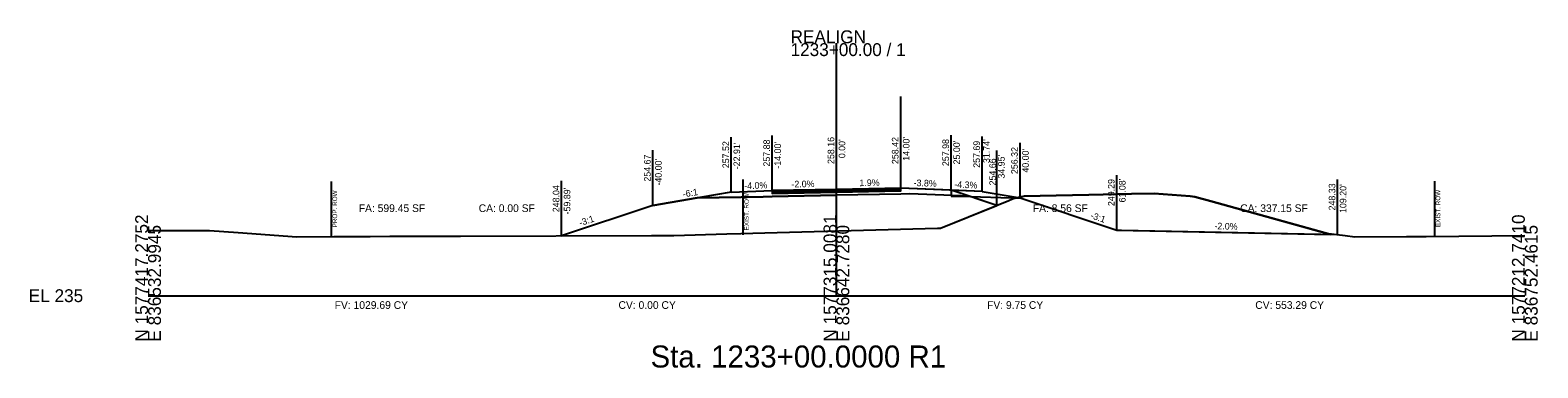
# Model space of a CAD drawing. Extents: x -26 to 6303, y -16 to 9563.
# Drawn here: x 974.3 to 1302.8, y 1984.3 to 2057.8 of the extents above; entities that cross this region are included whole.
import ezdxf

# ---------------------------------------------------------------- set-up
doc = ezdxf.new("R2010")
doc.units = 0
for name, color, linetype in [('ASPHALT_19MM1', 7, 'Continuous'), ('ASPHALT_9_5MM1', 7, 'Continuous'), ('CONST_DCH', 7, 'Continuous'), ('CONST_LV3', 7, 'Continuous'), ('Draft_XS_Grid', 7, 'Continuous'), ('Draft_XS_Text', 7, 'Continuous'), ('DTM_TEMP_DROP', 7, 'Continuous'), ('DTM_X_GROUND', 7, 'Continuous'), ('X_PROFILES_1', 7, 'Continuous'), ('X_TRANS_EOP', 7, 'Continuous'), ('XS_CELL', 7, 'Continuous'), ('XS_M_SHAPES_EARTHWORK', 7, 'Continuous'), ('XS_P_ASPHALT', 7, 'Continuous'), ('XS_P_DR_ASPHALT', 7, 'Continuous'), ('XS_P_GROUND', 7, 'Continuous'), ('XS_P_ROW', 7, 'Continuous'), ('XS_P_SHOULDER', 7, 'Continuous'), ('XS_P_SUBGRADE_GRANULAR', 7, 'Continuous'), ('XS_P_TX_CLEARZONE', 7, 'Continuous'), ('XS_P_TX_FS_BS', 7, 'Continuous'), ('XS_PLAN_CLEAR_ZONE', 7, 'Continuous'), ('XS_SHEET_EW_TX_AREA', 7, 'Continuous'), ('XS_SHEET_EW_TX_VOLUME', 7, 'Continuous'), ('XS_X_ROW', 7, 'Continuous')]:
    doc.layers.add(name, color=color, linetype=linetype)

msp = doc.modelspace()

# ---------------------------------------------------------------- linework, layer by layer
at = {"layer": 'ASPHALT_19MM1'}
msp.add_lwpolyline([(1136, 2022.55), (1136, 2022.28), (1150, 2022.56), (1150, 2022.56), (1164, 2022.82), (1164, 2022.82), (1164, 2023.09), (1164, 2023.09), (1164, 2023.09), (1150, 2022.83), (1150, 2022.83), (1136, 2022.55), (1136, 2022.55)], dxfattribs=at)
at = {"layer": 'ASPHALT_9_5MM1'}
msp.add_lwpolyline([(1136, 2022.88), (1136, 2022.75), (1150, 2023.03), (1150, 2023.03), (1164, 2023.3), (1164, 2023.3), (1164, 2023.42), (1164, 2023.42), (1164, 2023.42), (1150, 2023.16), (1150, 2023.16), (1136, 2022.88), (1136, 2022.88)], dxfattribs=at)
at = {"layer": 'CONST_LV3'}
for points in [[(1110, 2019.67), (1110, 2019.67), (1119.64, 2021.28)], [(1164, 2023.4), (1164, 2023.4), (1150, 2023.16)], [(1181.74, 2022.69), (1181.74, 2022.69), (1164, 2023.4)]]:
    msp.add_lwpolyline(points, dxfattribs=at)
at = {"layer": 'DTM_X_GROUND'}
msp.add_lwpolyline([(1000, 2014.19), (1013.42, 2014.18), (1019.67, 2013.74), (1032.39, 2012.85), (1040.48, 2012.89), (1048.37, 2012.92), (1052.65, 2012.94), (1068.1, 2012.99), (1109.67, 2013.1), (1114.58, 2013.12), (1126.12, 2013.44), (1129.18, 2013.52), (1134.43, 2013.67), (1172.04, 2014.68), (1172.69, 2014.71), (1187.59, 2020.73), (1188.34, 2021.11), (1188.56, 2021.15), (1190.88, 2021.68), (1197.89, 2021.83), (1204.97, 2021.98), (1214.29, 2022.17), (1219.21, 2022.27), (1227.06, 2021.65), (1228.11, 2021.57), (1231.57, 2020.61), (1256.64, 2013.65), (1260.83, 2013.12), (1262.97, 2012.84), (1274.23, 2012.89), (1278.48, 2012.92), (1285.63, 2012.98), (1300, 2013.08)], dxfattribs=at)
at = {"layer": 'X_TRANS_EOP'}
msp.add_line((1164, 2023.4), (1164, 2043.4), dxfattribs=at)
at = {"layer": 'XS_CELL'}
for p, q in [((1150, 2000), (1150, 2055)), ((1000, 2000), (1150, 2000)), ((1150, 2000), (1300, 2000))]:
    msp.add_line(p, q, dxfattribs=at)
at = {"layer": 'XS_M_SHAPES_EARTHWORK'}
msp.add_lwpolyline([(1090.11, 2013.04), (1109.67, 2013.1), (1114.58, 2013.12), (1126.12, 2013.44), (1129.18, 2013.52), (1134.43, 2013.67), (1172.04, 2014.68), (1172.69, 2014.71), (1184.95, 2019.66), (1178.93, 2021.67), (1166, 2022.19), (1164, 2022.15), (1150, 2021.89), (1136, 2021.61), (1134, 2021.57), (1119.64, 2021.28), (1110, 2019.67)], close=True, dxfattribs=at)
at = {"layer": 'XS_P_GROUND'}
for points in [[(1127.09, 2022.52), (1110, 2019.67), (1090.11, 2013.04)], [(1184.95, 2019.66), (1175, 2022.98), (1175, 2022.98)], [(1181.74, 2022.69), (1190, 2021.32), (1211.08, 2014.29)], [(1211.08, 2014.29), (1212.08, 2014.27)], [(1212.08, 2014.27), (1259.2, 2013.33)]]:
    msp.add_lwpolyline(points, dxfattribs=at)
at = {"layer": 'XS_P_ROW'}
msp.add_line((1040, 2012.88), (1040, 2024.88), dxfattribs=at)
at = {"layer": 'XS_P_SHOULDER'}
for points in [[(1127.09, 2022.52), (1127.09, 2022.52), (1136, 2022.88)], [(1175, 2022.98), (1164, 2023.42), (1164, 2023.42)], [(1181.74, 2022.69), (1181.74, 2022.69), (1175, 2022.96)]]:
    msp.add_lwpolyline(points, dxfattribs=at)
at = {"layer": 'XS_P_SUBGRADE_GRANULAR'}
for points in [[(1119.64, 2021.28), (1119.64, 2021.28), (1134, 2021.57), (1136, 2021.61), (1136, 2021.61)], [(1136, 2021.61), (1150, 2021.89), (1150, 2021.89)], [(1164, 2022.15), (1164, 2022.15), (1150, 2021.89)], [(1178.93, 2021.67), (1178.93, 2021.67), (1166, 2022.19), (1166, 2022.19), (1164, 2022.15)], [(1175, 2022.96), (1175, 2021.69)], [(1175, 2021.69), (1177, 2021.68), (1190.19, 2021.25)]]:
    msp.add_lwpolyline(points, dxfattribs=at)
at = {"layer": 'XS_P_TX_CLEARZONE'}
for p, q in [((1127.09, 2022.52), (1127.09, 2034.52)), ((1136, 2022.88), (1136, 2034.88)), ((1150, 2023.16), (1150, 2035.16)), ((1164, 2023.42), (1164, 2035.42)), ((1175, 2022.98), (1175, 2034.98)), ((1181.74, 2022.69), (1181.74, 2034.69)), ((1110, 2019.67), (1110, 2031.67)), ((1184.95, 2019.66), (1184.95, 2031.66)), ((1190, 2021.32), (1190, 2033.32)), ((1090.11, 2013.04), (1090.11, 2025.04)), ((1211.08, 2014.29), (1211.08, 2026.29)), ((1259.2, 2013.33), (1259.2, 2025.33))]:
    msp.add_line(p, q, dxfattribs=at)
at = {"layer": 'XS_P_TX_FS_BS'}
for p, q in [((1190, 2021.32), (1211.08, 2014.29)), ((1211.08, 2014.29), (1257.74, 2013.36))]:
    msp.add_line(p, q, dxfattribs=at)
for points in [[(1257.74, 2013.36), (1231.57, 2020.61), (1228.11, 2021.57), (1227.06, 2021.65), (1219.21, 2022.27), (1214.29, 2022.17), (1204.97, 2021.98), (1197.89, 2021.83), (1190.88, 2021.68), (1189.58, 2021.39)], [(1189.58, 2021.39), (1189.75, 2021.36), (1190, 2021.32)]]:
    msp.add_lwpolyline(points, dxfattribs=at)
at = {"layer": 'XS_PLAN_CLEAR_ZONE'}
msp.add_lwpolyline([(1136, 2022.75), (1136, 2022.55), (1150, 2022.83), (1150, 2022.83), (1164, 2023.09), (1164, 2023.09), (1164, 2023.3), (1164, 2023.3), (1164, 2023.3), (1150, 2023.03), (1150, 2023.03), (1136, 2022.75), (1136, 2022.75)], dxfattribs=at)
at = {"layer": 'XS_X_ROW'}
for p, q in [((1129.69, 2013.29), (1129.69, 2025.29)), ((1280.38, 2012.94), (1280.38, 2024.94))]:
    msp.add_line(p, q, dxfattribs=at)

# ---------------------------------------------------------------- texts
at = {"layer": 'CONST_DCH'}
for p in [(1135.92, 2022.76), (1149.92, 2023.04), (1163.92, 2023.3)]:
    msp.add_text('X', height=0.24, dxfattribs=at).set_placement(p)
at = {"layer": 'Draft_XS_Grid'}
msp.add_text('-', height=0.0001, dxfattribs=at).set_placement((1000, 2000))
at = {"layer": 'Draft_XS_Text'}
msp.add_text('Sta. 1233+00.0000 R1', height=4.8, dxfattribs=at).set_placement((1109.49, 1984.35))
at = {"layer": 'DTM_TEMP_DROP'}
for p in [(1174.92, 2022.84), (1184.87, 2019.54), (1090.03, 2012.92)]:
    msp.add_text('X', height=0.24, dxfattribs=at).set_placement(p)
at = {"layer": 'X_PROFILES_1'}
for p in [(1181.66, 2022.57), (1189.92, 2021.2)]:
    msp.add_text('X', height=0.24, dxfattribs=at).set_placement(p)
at = {"layer": 'XS_CELL'}
for s, p in [('REALIGN', (1140, 2055)), ('1233+00.00 / 1', (1140, 2052.2)), ('EL 235', (974, 1998.6))]:
    msp.add_text(s, height=2.8, dxfattribs=at).set_placement(p)
for s, p in [('N 1577417.2752', (1000, 1990)), ('N 1577315.0081', (1150, 1990)), ('N 1577212.7410', (1300, 1990)), ('E 836532.9945', (1002.8, 1990)), ('E 836642.7280', (1152.8, 1990)), ('E 836752.4615', (1302.8, 1990))]:
    msp.add_text(s, height=2.8, rotation=90, dxfattribs=at).set_placement(p)
at = {"layer": 'XS_P_ASPHALT'}
msp.add_text('X', height=0.24, dxfattribs=at).set_placement((1211, 2014.17))
at = {"layer": 'XS_P_DR_ASPHALT'}
msp.add_text('X', height=0.24, dxfattribs=at).set_placement((1109.92, 2019.55))
at = {"layer": 'XS_P_ROW'}
msp.add_text('PROP. ROW', height=1, rotation=90, dxfattribs=at).set_placement((1041.2, 2014.88))
at = {"layer": 'XS_P_SHOULDER'}
for p in [(1127.01, 2022.4), (1174.92, 2022.86)]:
    msp.add_text('X', height=0.24, dxfattribs=at).set_placement(p)
at = {"layer": 'XS_P_SUBGRADE_GRANULAR'}
for p in [(1184.87, 2019.54), (1090.03, 2012.92), (1259.13, 2013.21)]:
    msp.add_text('X', height=0.24, dxfattribs=at).set_placement(p)
at = {"layer": 'XS_P_TX_CLEARZONE'}
for s, p in [('257.88', (1135.52, 2028.13)), ('258.16', (1149.52, 2028.69)), ("0.00'", (1151.92, 2029.95)), ('258.42', (1163.52, 2028.67)), ("14.00'", (1165.92, 2029.39)), ('257.98', (1174.52, 2028.23)), ("25.00'", (1176.92, 2028.59)), ('257.69', (1181.26, 2027.86)), ("31.74'", (1183.41, 2028.89)), ('254.67', (1109.52, 2024.85)), ('257.52', (1126.61, 2027.77)), ("-22.91'", (1129.01, 2027.54)), ("-14.00'", (1137.92, 2027.67)), ("34.95'", (1186.66, 2025.5)), ('256.32', (1189.52, 2026.49)), ("40.00'", (1191.92, 2026.81)), ("-40.00'", (1111.92, 2023.99)), ('254.66', (1184.75, 2024.02)), ('248.04', (1089.63, 2018.18)), ('249.29', (1210.6, 2019.52)), ("61.08'", (1213, 2020.31)), ('248.33', (1258.72, 2018.57)), ("109.20'", (1261.12, 2018.01)), ("-59.89'", (1092.03, 2017.7))]:
    msp.add_text(s, height=1.44, rotation=90, dxfattribs=at).set_placement(p)
at = {"layer": 'XS_P_TX_FS_BS'}
for s, rotation, p in [('-4.0%', 2.2906, (1129.94, 2023.19)), ('-2.0%', 1.1458, (1140.2, 2023.56)), ('1.9%', 1.0745, (1155.02, 2023.85)), ('-3.8%', 357.8128, (1166.79, 2023.9)), ('-4.3%', 357.5407, (1175.66, 2023.55)), ('-6:1', 9.4642, (1116.63, 2021.39)), ('-3:1', 18.4332, (1094.19, 2015.13)), ('-3:1', 341.5651, (1205.22, 2016.9)), ('-2.0%', 358.8542, (1232.36, 2014.46))]:
    msp.add_text(s, height=1.44, rotation=rotation, dxfattribs=at).set_placement(p)
at = {"layer": 'XS_SHEET_EW_TX_AREA'}
for s, p in [('FA: 599.45 SF', (1045.91, 2018.22)), ('CA: 0.00 SF', (1072.05, 2018.22)), ('FA: 8.56 SF', (1192.79, 2018.22)), ('CA: 337.15 SF', (1237.98, 2018.22))]:
    msp.add_text(s, height=1.68, dxfattribs=at).set_placement(p)
at = {"layer": 'XS_SHEET_EW_TX_VOLUME'}
for s, p in [('FV: 1029.69 CY', (1040.66, 1997.12)), ('CV: 0.00 CY', (1102.51, 1997.12)), ('FV: 9.75 CY', (1182.82, 1997.12)), ('CV: 553.29 CY', (1241.27, 1997.12))]:
    msp.add_text(s, height=1.68, dxfattribs=at).set_placement(p)
at = {"layer": 'XS_X_ROW'}
for p in [(1130.89, 2014.21), (1281.58, 2014.94)]:
    msp.add_text('EXIST. ROW', height=1, rotation=90, dxfattribs=at).set_placement(p)

doc.saveas('drawing.dxf')
